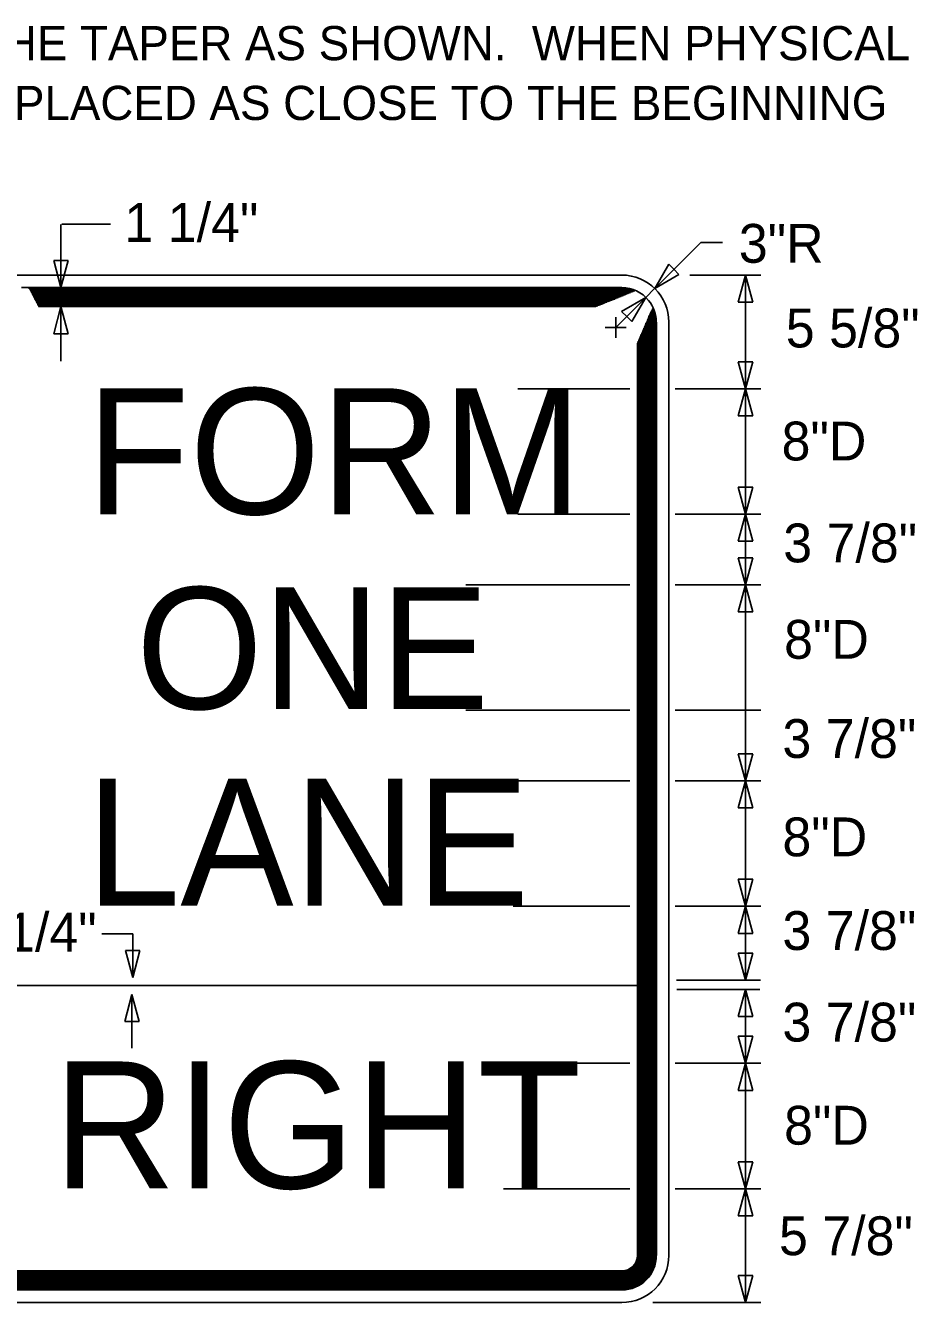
# Model space of a CAD drawing. Extents: x 15261 to 18126, y 1908 to 6555.
# Drawn here: x 17845.2 to 18038.2, y 2373.6 to 2649.8 of the extents above; entities that cross this region are included whole.
import ezdxf

# ---------------------------------------------------------------- set-up
doc = ezdxf.new("R2010")
doc.units = 0
for name, color, linetype in [('TYPICAL_EX', 7, 'Continuous'), ('TYPICAL_TEXT_DIMEN_EX', 7, 'Continuous'), ('TYPICAL_TEXT_DIMEN_PR', 7, 'Continuous')]:
    doc.layers.add(name, color=color, linetype=linetype)

msp = doc.modelspace()

# ---------------------------------------------------------------- linework, layer by layer
at = {"layer": 'TYPICAL_EX'}
for p, q in [((17974.24, 2595.85), (17831.73, 2595.85)), ((17974.24, 2593.13), (17844.36, 2593.13)), ((17974.24, 2593.02), (17845.88, 2593.02)), ((17974.24, 2592.91), (17846.02, 2592.91)), ((17974.24, 2592.8), (17846.08, 2592.8)), ((17974.24, 2592.68), (17846.14, 2592.68)), ((17974.24, 2592.57), (17846.2, 2592.57)), ((17974.24, 2592.46), (17846.26, 2592.46)), ((17974.24, 2592.35), (17846.31, 2592.35)), ((17974.24, 2592.24), (17846.37, 2592.24)), ((17974.24, 2592.12), (17846.43, 2592.12)), ((17974.24, 2592.01), (17846.49, 2592.01)), ((17974.24, 2591.9), (17846.55, 2591.9)), ((17974.24, 2591.79), (17846.6, 2591.79)), ((17974.24, 2591.67), (17846.66, 2591.67)), ((17974.24, 2591.56), (17846.72, 2591.56)), ((17974.24, 2591.45), (17846.78, 2591.45)), ((17974.24, 2591.34), (17846.84, 2591.34)), ((17974.11, 2591.23), (17846.89, 2591.23)), ((17973.83, 2591.11), (17846.95, 2591.11)), ((17973.55, 2591), (17847.01, 2591)), ((17973.27, 2590.89), (17847.07, 2590.89)), ((17972.99, 2590.78), (17847.12, 2590.78)), ((17972.71, 2590.67), (17847.18, 2590.67)), ((17972.43, 2590.55), (17847.24, 2590.55)), ((17972.15, 2590.44), (17847.3, 2590.44)), ((17971.87, 2590.33), (17847.36, 2590.33)), ((17971.58, 2590.22), (17847.42, 2590.22)), ((17971.3, 2590.11), (17847.47, 2590.11)), ((17971.02, 2589.99), (17847.53, 2589.99)), ((17970.74, 2589.88), (17847.59, 2589.88)), ((17970.46, 2589.77), (17847.65, 2589.77)), ((17970.18, 2589.66), (17847.71, 2589.66)), ((17969.9, 2589.55), (17847.76, 2589.55)), ((17969.62, 2589.43), (17847.82, 2589.43)), ((17969.34, 2589.32), (17847.88, 2589.32)), ((17969.06, 2589.21), (17847.94, 2589.21)), ((17968.78, 2589.1), (17847.99, 2589.1)), ((17968.59, 2589.02), (17848.03, 2589.02)), ((17978.57, 2437.62), (17978.57, 2583.34)), ((17978.68, 2437.51), (17978.68, 2583.6)), ((17978.8, 2437.53), (17978.8, 2583.86)), ((17978.91, 2437.57), (17978.91, 2584.12)), ((17979.02, 2437.62), (17979.02, 2584.38)), ((17979.13, 2437.55), (17979.13, 2584.64)), ((17979.24, 2437.57), (17979.24, 2584.9)), ((17979.35, 2437.55), (17979.35, 2585.16)), ((17979.47, 2437.45), (17979.47, 2585.42)), ((17979.58, 2437.6), (17979.58, 2585.67)), ((17979.69, 2437.62), (17979.69, 2585.67)), ((17979.8, 2437.6), (17979.8, 2585.67)), ((17979.92, 2437.49), (17979.92, 2585.67)), ((17980.03, 2437.55), (17980.03, 2585.67)), ((17980.14, 2437.62), (17980.14, 2585.67)), ((17980.25, 2437.66), (17980.25, 2585.67)), ((17980.36, 2437.57), (17980.36, 2585.67)), ((17980.48, 2437.62), (17980.48, 2585.67)), ((17980.59, 2437.57), (17980.59, 2585.67)), ((17980.7, 2437.6), (17980.7, 2585.67)), ((17980.81, 2437.6), (17980.81, 2585.67)), ((17980.92, 2437.6), (17980.92, 2585.67)), ((17981.03, 2437.64), (17981.03, 2585.67)), ((17981.15, 2437.66), (17981.15, 2585.67)), ((17981.26, 2437.6), (17981.26, 2585.67)), ((17981.37, 2437.6), (17981.37, 2585.67)), ((17981.48, 2437.64), (17981.48, 2585.67)), ((17981.6, 2437.6), (17981.6, 2585.67)), ((17981.71, 2437.65), (17981.71, 2585.67)), ((17984.42, 2437.62), (17984.42, 2585.67)), ((17977.6, 2437.58), (17977.6, 2581.09)), ((17977.67, 2437.58), (17977.67, 2581.26)), ((17977.79, 2437.68), (17977.79, 2581.52)), ((17977.9, 2437.66), (17977.9, 2581.78)), ((17978.01, 2437.58), (17978.01, 2582.04)), ((17978.12, 2437.58), (17978.12, 2582.3)), ((17978.24, 2437.66), (17978.24, 2582.56)), ((17978.35, 2437.51), (17978.35, 2582.82)), ((17978.46, 2437.6), (17978.46, 2583.08)), ((17828.79, 2442.14), (17977.54, 2442.14)), ((17977.6, 2383.73), (17977.6, 2437.58)), ((17977.67, 2383.73), (17977.67, 2437.58)), ((17977.78, 2383.73), (17977.78, 2437.58)), ((17977.9, 2383.73), (17977.9, 2437.58)), ((17978.01, 2383.73), (17978.01, 2437.58)), ((17978.12, 2383.73), (17978.12, 2437.58)), ((17978.23, 2383.73), (17978.23, 2437.58)), ((17978.35, 2383.73), (17978.35, 2437.58)), ((17978.46, 2383.73), (17978.46, 2437.58)), ((17978.57, 2383.73), (17978.57, 2437.58)), ((17978.68, 2383.73), (17978.68, 2437.58)), ((17978.79, 2383.73), (17978.79, 2437.58)), ((17978.91, 2383.73), (17978.91, 2437.58)), ((17979.02, 2383.73), (17979.02, 2437.58)), ((17979.13, 2383.73), (17979.13, 2437.58)), ((17979.24, 2383.73), (17979.24, 2437.58)), ((17979.35, 2383.73), (17979.35, 2437.58)), ((17979.47, 2383.73), (17979.47, 2437.58)), ((17979.58, 2383.73), (17979.58, 2437.58)), ((17979.69, 2383.73), (17979.69, 2437.58)), ((17979.8, 2383.73), (17979.8, 2437.58)), ((17979.92, 2383.73), (17979.92, 2437.58)), ((17980.03, 2383.73), (17980.03, 2437.58)), ((17980.14, 2383.73), (17980.14, 2437.58)), ((17980.25, 2383.73), (17980.25, 2437.58)), ((17980.36, 2383.73), (17980.36, 2437.58)), ((17980.48, 2383.73), (17980.48, 2437.58)), ((17980.59, 2383.73), (17980.59, 2437.58)), ((17980.7, 2383.73), (17980.7, 2437.58)), ((17980.81, 2383.73), (17980.81, 2437.58)), ((17980.92, 2383.73), (17980.92, 2437.58)), ((17981.03, 2383.73), (17981.03, 2437.58)), ((17981.15, 2383.73), (17981.15, 2437.58)), ((17981.26, 2383.73), (17981.26, 2437.58)), ((17981.37, 2383.73), (17981.37, 2437.58)), ((17981.48, 2383.73), (17981.48, 2437.58)), ((17981.6, 2383.73), (17981.6, 2437.58)), ((17981.71, 2383.73), (17981.71, 2437.58)), ((17984.42, 2383.73), (17984.42, 2437.58)), ((17831.73, 2380.38), (17974.24, 2380.38)), ((17831.73, 2380.3), (17974.24, 2380.3)), ((17831.73, 2380.19), (17974.24, 2380.19)), ((17831.73, 2380.08), (17974.24, 2380.08)), ((17831.73, 2379.97), (17974.24, 2379.97)), ((17831.73, 2379.85), (17974.24, 2379.85)), ((17831.73, 2379.74), (17974.24, 2379.74)), ((17831.73, 2379.63), (17974.24, 2379.63)), ((17831.73, 2379.52), (17974.24, 2379.52)), ((17831.73, 2379.41), (17974.24, 2379.41)), ((17831.73, 2379.29), (17974.24, 2379.29)), ((17831.73, 2379.18), (17974.24, 2379.18)), ((17831.73, 2379.07), (17974.24, 2379.07)), ((17831.73, 2378.96), (17974.24, 2378.96)), ((17831.73, 2378.84), (17974.24, 2378.84)), ((17831.73, 2378.73), (17974.24, 2378.73)), ((17831.73, 2378.62), (17974.24, 2378.62)), ((17831.73, 2378.51), (17974.24, 2378.51)), ((17831.73, 2378.4), (17974.24, 2378.4)), ((17831.73, 2378.28), (17974.24, 2378.28)), ((17831.73, 2378.17), (17974.24, 2378.17)), ((17831.73, 2378.06), (17974.24, 2378.06)), ((17831.73, 2377.95), (17974.24, 2377.95)), ((17831.73, 2377.84), (17974.24, 2377.84)), ((17831.73, 2377.72), (17974.24, 2377.72)), ((17831.73, 2377.61), (17974.24, 2377.61)), ((17831.73, 2377.5), (17974.24, 2377.5)), ((17831.73, 2377.39), (17974.24, 2377.39)), ((17831.73, 2377.28), (17974.24, 2377.28)), ((17831.73, 2377.16), (17974.24, 2377.16)), ((17831.73, 2377.05), (17974.24, 2377.05)), ((17831.73, 2376.94), (17974.24, 2376.94)), ((17831.73, 2376.83), (17974.24, 2376.83)), ((17831.73, 2376.72), (17974.24, 2376.72)), ((17831.73, 2376.6), (17974.24, 2376.6)), ((17831.73, 2376.49), (17974.24, 2376.49)), ((17831.73, 2376.38), (17974.24, 2376.38)), ((17831.73, 2376.27), (17974.24, 2376.27)), ((17831.73, 2373.55), (17974.24, 2373.55))]:
    msp.add_line(p, q, dxfattribs=at)
for centre, radius, start, end in [((17974.24, 2585.67), 10.18, 0, 90), ((17974.24, 2585.67), 7.46, 39.0673, 90), ((17974.24, 2585.67), 7.35, 66.9087, 90), ((17974.24, 2585.67), 7.24, 67.8069, 90), ((17974.24, 2585.67), 7.13, 68.7489, 90), ((17974.24, 2585.67), 7.02, 69.7388, 90), ((17974.24, 2585.67), 6.9, 70.7811, 90), ((17974.24, 2585.67), 6.79, 71.8812, 90), ((17974.24, 2585.67), 6.68, 73.0455, 90), ((17974.24, 2585.67), 6.57, 74.2814, 90), ((17974.24, 2585.67), 6.46, 75.5979, 90), ((17974.24, 2585.67), 6.34, 77.006, 90), ((17974.24, 2585.67), 6.23, 78.5194, 90), ((17974.24, 2585.67), 6.12, 80.1555, 90), ((17974.24, 2585.67), 6.01, 81.9371, 90), ((17974.24, 2585.67), 5.9, 83.8949, 90), ((17974.24, 2585.67), 5.78, 86.0727, 90), ((17974.24, 2585.67), 5.67, 88.5362, 90), ((17974.24, 2585.67), 7.46, 0, 39.0664), ((17974.24, 2585.67), 5.56, 0, 4.9634), ((17974.24, 2585.67), 5.67, 0, 6.9999), ((17974.24, 2585.67), 5.78, 0, 8.847), ((17974.24, 2585.67), 5.9, 0, 10.5386), ((17974.24, 2585.67), 6.01, 0, 12.0996), ((17974.24, 2585.67), 6.12, 0, 13.5489), ((17974.24, 2585.67), 6.23, 0, 14.9011), ((17974.24, 2585.67), 6.34, 0, 16.1683), ((17974.24, 2585.67), 6.46, 0, 17.36), ((17974.24, 2585.67), 6.57, 0, 18.4842), ((17974.24, 2585.67), 6.68, 0, 19.5478), ((17974.24, 2585.67), 6.79, 0, 20.5564), ((17974.24, 2585.67), 6.9, 0, 21.5151), ((17974.24, 2585.67), 7.02, 0, 22.4279), ((17974.24, 2585.67), 7.13, 0, 23.2988), ((17974.24, 2585.67), 7.24, 0, 24.1309), ((17974.24, 2585.67), 7.35, 0, 24.1308), ((17974.24, 2585.67), 5.34, 0, 0.1031), ((17974.24, 2585.67), 5.45, 0, 2.6891), ((17974.24, 2383.73), 7.46, 270, 0), ((17974.24, 2383.73), 3.36, 270, 0), ((17974.24, 2383.73), 7.35, 270, 0), ((17974.24, 2383.73), 7.24, 270, 0), ((17974.24, 2383.73), 7.13, 270, 0), ((17974.24, 2383.73), 7.02, 270, 0), ((17974.24, 2383.73), 6.9, 270, 0), ((17974.24, 2383.73), 6.79, 270, 0), ((17974.24, 2383.73), 6.68, 270, 0), ((17974.24, 2383.73), 6.57, 270, 0), ((17974.24, 2383.73), 6.46, 270, 0), ((17974.24, 2383.73), 6.34, 270, 0), ((17974.24, 2383.73), 6.23, 270, 0), ((17974.24, 2383.73), 6.12, 270, 0), ((17974.24, 2383.73), 6.01, 270, 0), ((17974.24, 2383.73), 5.9, 270, 0), ((17974.24, 2383.73), 5.78, 270, 0), ((17974.24, 2383.73), 5.67, 270, 0), ((17974.24, 2383.73), 5.56, 270, 0), ((17974.24, 2383.73), 5.45, 270, 0), ((17974.24, 2383.73), 5.34, 270, 0), ((17974.24, 2383.73), 5.22, 270, 0), ((17974.24, 2383.73), 5.11, 270, 0), ((17974.24, 2383.73), 5, 270, 0), ((17974.24, 2383.73), 4.89, 270, 0), ((17974.24, 2383.73), 4.78, 270, 0), ((17974.24, 2383.73), 4.66, 270, 0), ((17974.24, 2383.73), 4.55, 270, 0), ((17974.24, 2383.73), 4.44, 270, 0), ((17974.24, 2383.73), 4.33, 270, 0), ((17974.24, 2383.73), 4.21, 270, 0), ((17974.24, 2383.73), 4.1, 270, 0), ((17974.24, 2383.73), 3.99, 270, 0), ((17974.24, 2383.73), 3.88, 270, 0), ((17974.24, 2383.73), 3.77, 270, 0), ((17974.24, 2383.73), 3.65, 270, 0), ((17974.24, 2383.73), 3.54, 270, 0), ((17974.24, 2383.73), 3.43, 270, 0), ((17974.24, 2383.73), 10.18, 270, 0)]:
    msp.add_arc(centre, radius, start, end, dxfattribs=at)
at = {"layer": 'TYPICAL_TEXT_DIMEN_PR'}
for p, q in [((17852.88, 2593.13), (17852.88, 2606.77)), ((17853.05, 2606.84), (17863.62, 2606.84)), ((17981.35, 2592.95), (17991.31, 2602.91)), ((17991.31, 2602.91), (17996.01, 2602.91)), ((17852.88, 2593.13), (17851.31, 2598.99)), ((17851.31, 2598.99), (17852.88, 2598.99)), ((17852.88, 2598.99), (17854.45, 2598.99)), ((17854.45, 2598.99), (17852.88, 2593.13)), ((17981.35, 2592.95), (17984.39, 2598.21)), ((17984.39, 2598.21), (17985.5, 2597.1)), ((17985.5, 2597.1), (17986.61, 2595.99)), ((17986.61, 2595.99), (17981.35, 2592.95)), ((17988.95, 2595.85), (18004.31, 2595.85)), ((17999.42, 2589.98), (18000.99, 2595.85)), ((18000.99, 2571.25), (18000.99, 2595.85)), ((18000.99, 2595.85), (18002.56, 2589.98)), ((17852.88, 2593.39), (17852.88, 2593.4)), ((17852.88, 2593.39), (17852.88, 2593.39)), ((17979.44, 2591.03), (17981.32, 2592.92)), ((17851.31, 2583.16), (17852.88, 2589.02)), ((17852.88, 2577.24), (17852.88, 2589.02)), ((17852.88, 2589.02), (17854.45, 2583.16)), ((17972.91, 2584.51), (17979.44, 2591.03)), ((17974.18, 2588), (17979.43, 2591.03)), ((17979.43, 2591.03), (17976.4, 2585.78)), ((18000.99, 2589.98), (17999.42, 2589.98)), ((18002.56, 2589.98), (18000.99, 2589.98)), ((17972.91, 2582.26), (17972.91, 2586.75)), ((17975.29, 2586.89), (17974.18, 2588)), ((17976.4, 2585.78), (17975.29, 2586.89)), ((17970.67, 2584.51), (17972.91, 2584.51)), ((17972.91, 2584.51), (17975.15, 2584.51)), ((17852.88, 2583.16), (17851.31, 2583.16)), ((17854.45, 2583.16), (17852.88, 2583.16)), ((18000.99, 2571.25), (17999.42, 2577.11)), ((17999.42, 2577.11), (18000.99, 2577.11)), ((18000.99, 2577.11), (18002.56, 2577.11)), ((18002.56, 2577.11), (18000.99, 2571.25)), ((17951.77, 2571.25), (17975.94, 2571.25)), ((17985.79, 2571.25), (18004.31, 2571.25)), ((17999.42, 2565.38), (18000.99, 2571.25)), ((18000.99, 2544.1), (18000.99, 2571.25)), ((18000.99, 2571.25), (18002.56, 2565.38)), ((18000.99, 2565.38), (17999.42, 2565.38)), ((18002.56, 2565.38), (18000.99, 2565.38)), ((18000.99, 2544.1), (17999.42, 2549.96)), ((17999.42, 2549.96), (18000.99, 2549.96)), ((18000.99, 2549.96), (18002.56, 2549.96)), ((18002.56, 2549.96), (18000.99, 2544.1)), ((17951.77, 2544.1), (17975.94, 2544.1)), ((17985.79, 2544.1), (18004.31, 2544.1)), ((17999.42, 2538.24), (18000.99, 2544.1)), ((18000.99, 2528.83), (18000.99, 2544.1)), ((18000.99, 2544.1), (18002.56, 2538.24)), ((18000.99, 2538.24), (17999.42, 2538.24)), ((18002.56, 2538.24), (18000.99, 2538.24)), ((18000.99, 2528.83), (17999.42, 2534.69)), ((17999.42, 2534.69), (18000.99, 2534.69)), ((18000.99, 2534.69), (18002.56, 2534.69)), ((18002.56, 2534.69), (18000.99, 2528.83)), ((17940.51, 2528.83), (17975.94, 2528.83)), ((17985.79, 2528.83), (18004.31, 2528.83)), ((17999.42, 2522.97), (18000.99, 2528.83)), ((18000.99, 2501.69), (18000.99, 2528.83)), ((18000.99, 2528.83), (18002.56, 2522.97)), ((18000.99, 2522.97), (17999.42, 2522.97)), ((18002.56, 2522.97), (18000.99, 2522.97)), ((17940.51, 2501.69), (17975.94, 2501.69)), ((17985.79, 2501.69), (18004.31, 2501.69)), ((18000.99, 2486.42), (18000.99, 2501.69)), ((18000.99, 2486.42), (17999.42, 2492.28)), ((17999.42, 2492.28), (18000.99, 2492.28)), ((18000.99, 2492.28), (18002.56, 2492.28)), ((18002.56, 2492.28), (18000.99, 2486.42)), ((17950.76, 2486.42), (17975.94, 2486.42)), ((17985.79, 2486.42), (18004.31, 2486.42)), ((17999.42, 2480.56), (18000.99, 2486.42)), ((18000.99, 2459.27), (18000.99, 2486.42)), ((18000.99, 2486.42), (18002.56, 2480.56)), ((18000.99, 2480.56), (17999.42, 2480.56)), ((18002.56, 2480.56), (18000.99, 2480.56)), ((18000.99, 2459.27), (17999.42, 2465.13)), ((17999.42, 2465.13), (18000.99, 2465.13)), ((18000.99, 2465.13), (18002.56, 2465.13)), ((18002.56, 2465.13), (18000.99, 2459.27)), ((17950.76, 2459.27), (17975.94, 2459.27)), ((17985.79, 2459.27), (18004.31, 2459.27)), ((17999.42, 2453.41), (18000.99, 2459.27)), ((18000.99, 2443.3), (18000.99, 2459.27)), ((18000.99, 2459.27), (18000.99, 2459.27)), ((18000.99, 2459.27), (18000.99, 2459.27)), ((18000.99, 2459.27), (18002.56, 2453.41)), ((17868.4, 2453.31), (17861.74, 2453.31)), ((17868.4, 2443.85), (17868.4, 2453.31)), ((18000.99, 2453.41), (17999.42, 2453.41)), ((18002.56, 2453.41), (18000.99, 2453.41)), ((17868.4, 2443.85), (17866.83, 2449.72)), ((17866.83, 2449.72), (17868.4, 2449.72)), ((17868.4, 2449.72), (17869.98, 2449.72)), ((17869.98, 2449.72), (17868.4, 2443.85)), ((18000.99, 2443.3), (17999.42, 2449.16)), ((17999.42, 2449.16), (18000.99, 2449.16)), ((18000.99, 2449.16), (18002.56, 2449.16)), ((18002.56, 2449.16), (18000.99, 2443.3)), ((17986.04, 2443.3), (18004.22, 2443.3)), ((17866.67, 2434.33), (17868.24, 2440.19)), ((17868.24, 2428.54), (17868.24, 2440.19)), ((17868.24, 2440.19), (17869.81, 2434.33)), ((17986.13, 2441.29), (18004.13, 2441.29)), ((17999.42, 2435.42), (18000.99, 2441.28)), ((18000.99, 2425.3), (18000.99, 2441.28)), ((18000.99, 2441.28), (18002.56, 2435.42)), ((18002.2, 2437.58), (18002.21, 2437.56)), ((17868.24, 2434.33), (17866.67, 2434.33)), ((17869.81, 2434.33), (17868.24, 2434.33)), ((18000.99, 2435.42), (17999.42, 2435.42)), ((18002.56, 2435.42), (18000.99, 2435.42)), ((18000.99, 2425.3), (17999.42, 2431.16)), ((17999.42, 2431.16), (18000.99, 2431.16)), ((18000.99, 2431.16), (18002.56, 2431.16)), ((18002.56, 2431.16), (18000.99, 2425.3)), ((17956.07, 2425.3), (17975.94, 2425.3)), ((17985.79, 2425.3), (18004.31, 2425.3)), ((17999.42, 2419.44), (18000.99, 2425.3)), ((18000.99, 2398.15), (18000.99, 2425.3)), ((18000.99, 2425.3), (18002.56, 2419.44)), ((18000.99, 2419.44), (17999.42, 2419.44)), ((18002.56, 2419.44), (18000.99, 2419.44)), ((18000.99, 2398.15), (17999.42, 2404.01)), ((17999.42, 2404.01), (18000.99, 2404.01)), ((18000.99, 2404.01), (18002.56, 2404.01)), ((18002.56, 2404.01), (18000.99, 2398.15)), ((17948.66, 2398.15), (17975.94, 2398.15)), ((17985.79, 2398.15), (18004.31, 2398.15)), ((17999.42, 2392.29), (18000.99, 2398.15)), ((18000.99, 2373.55), (18000.99, 2398.15)), ((18000.99, 2398.15), (18002.56, 2392.29)), ((18000.99, 2392.29), (17999.42, 2392.29)), ((18002.56, 2392.29), (18000.99, 2392.29)), ((18000.99, 2373.55), (17999.42, 2379.41)), ((17999.42, 2379.41), (18000.99, 2379.41)), ((18000.99, 2379.41), (18002.56, 2379.41)), ((18002.56, 2379.41), (18000.99, 2373.55)), ((17980.93, 2373.55), (18004.31, 2373.55))]:
    msp.add_line(p, q, dxfattribs=at)

# ---------------------------------------------------------------- texts
at = {"layer": 'TYPICAL_TEXT_DIMEN_EX'}
for s, height, p in [('FORM', 27.241, (17858.45, 2544.1)), ('ONE', 26.355, (17869.14, 2501.95)), ('LANE', 27.463, (17858.3, 2459.44)), ('RIGHT', 27.463, (17851.23, 2398.23))]:
    msp.add_text(s, height=height, dxfattribs=at).set_placement(p)
at = {"layer": 'TYPICAL_TEXT_DIMEN_PR'}
for s, height, p in [('THE LIGHTED ARROW PANEL SHALL BE LOCATED AT THE BEGINNING OF THE TAPER AS SHOWN.  WHEN PHYSICAL', 7.392, (17478.58, 2642.34)), ('LIMITATIONS RESTRICT ITS PLACEMENT AS INDICATED, THEN IT SHALL BE PLACED AS CLOSE TO THE BEGINNING', 7.392, (17478.58, 2629.4)), ('1 1/4"', 8.4, (17866.63, 2603.03)), ('3"R', 8.4, (17999.56, 2598.51)), ('5 5/8"', 8.4, (18009.72, 2580.19)), ('8"D', 8.4, (18008.81, 2555.74)), ('3 7/8"', 8.4, (18009.17, 2533.69)), ('8"D', 8.4, (18009.35, 2512.83)), ('3 7/8"', 8.4, (18008.99, 2491.37)), ('8"D', 8.4, (18008.99, 2470.09)), ('1 1/4"', 8.4, (17831.64, 2449.47)), ('3 7/8"', 8.4, (18008.99, 2449.82)), ('3 7/8"', 8.4, (18008.99, 2430.01)), ('8"D', 8.4, (18009.35, 2407.7)), ('5 7/8"', 8.4, (18008.25, 2383.78))]:
    msp.add_text(s, height=height, dxfattribs=at).set_placement(p)

doc.saveas('drawing.dxf')
